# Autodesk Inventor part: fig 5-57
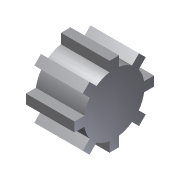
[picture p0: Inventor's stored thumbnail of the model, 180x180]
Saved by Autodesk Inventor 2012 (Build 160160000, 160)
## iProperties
Created: 2005-12
Part Number: fig 5-57
Document SubType Name: Modeling
Designer: CADCIM
Density: 1 g/cm^3
Material: Default
Author: CADCIM
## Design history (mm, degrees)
sketch "Sketch1"
  geometry: C1 r 27.506 at (0, 0)
  constraints: 1 centre point
extrude "Extrusion1" new body sketch "Sketch1" distance "d0" = 20; taper "d1" = 0 deg
sketch "Sketch2"
  geometry: L1 (-12.302, -1.705)-(-16.396, -1.705); L2 (-16.396, -1.705)-(-16.396, 2.216); L3 (-16.396, 2.216)-(-12.302, 2.216); L4 (-7.311, -9.833)-(-10.206, -12.728); L5 (-10.206, -12.728)-(-12.979, -9.955); L6 (-12.979, -9.955)-(-10.084, -7.06); L7 (1.966, -12.051)-(1.966, -16.145); L8 (1.966, -16.145)-(-1.956, -16.145); L9 (-1.956, -16.145)-(-1.956, -12.051); L10 (10.093, -7.06)-(12.988, -9.955); L11 (12.988, -9.955)-(10.215, -12.728); L12 (10.215, -12.728)-(7.32, -9.833); L13 (12.311, 2.216)-(16.405, 2.216); L14 (16.405, 2.216)-(16.405, -1.705); L15 (16.405, -1.705)-(12.311, -1.705); L16 (7.32, 10.344)-(10.215, 13.239); L17 (10.215, 13.239)-(12.988, 10.466); L18 (12.988, 10.466)-(10.093, 7.571); L19 (-1.956, 12.562)-(-1.956, 16.656); L20 (-1.956, 16.656)-(1.966, 16.656); L21 (1.966, 16.656)-(1.966, 12.562); L22 (-10.084, 7.571)-(-12.979, 10.466); L23 (-12.979, 10.466)-(-10.206, 13.239); L24 (-10.206, 13.239)-(-7.311, 10.344); A1 r 12.462 centre (0.005, 0.256) between (-12.302, -1.705) and (-10.084, -7.06); A2 r 12.462 centre (0.005, 0.256) between (-7.311, -9.833) and (-1.956, -12.051); A3 r 12.462 centre (0.005, 0.256) between (1.966, -12.051) and (7.32, -9.833); A4 r 12.462 centre (0.005, 0.256) between (10.093, -7.06) and (12.311, -1.705); A5 r 12.462 centre (0.005, 0.256) between (12.311, 2.216) and (10.093, 7.571); A6 r 12.462 centre (0.005, 0.256) between (7.32, 10.344) and (1.966, 12.562); A7 r 12.462 centre (0.005, 0.256) between (-1.956, 12.562) and (-7.311, 10.344); A8 r 12.462 centre (0.005, 0.256) between (-10.084, 7.571) and (-12.302, 2.216)
  constraints: 48 end point, 16 point on circle, 8 centre point, 2 parallel, 1 horizontal, 1 perpendicular, 57 other
  dimensions: "d4" = 360 deg dimension on A1.centre L2.end (derived)
extrude "Extrusion2" sketch "Sketch2" distance "d6" = 20; taper "d7" = 0 deg
body "Solid1"
